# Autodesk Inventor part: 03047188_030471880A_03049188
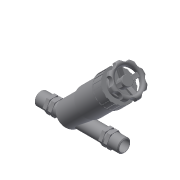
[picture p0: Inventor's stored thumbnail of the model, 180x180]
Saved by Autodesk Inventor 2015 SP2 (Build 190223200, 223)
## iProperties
Created: 2017-05
Part Number: 03047188_030471880A_03049188
Material: Generic
Description: PLASSON ANGLE SEAT VALVE 1.1/4"-1.1/4"
Document SubType Name: Modeling
Designer: KIM
Density: 1 g/cm^3
Appearance: Default
Author: KIM
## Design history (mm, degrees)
derived "03049.ipt"
feature "Solid1::03049.ipt"
tag "TaggingFeature1"
body "Solid1"
other parameters: "d0" = 225, "d1" = 47.803, "d3" = 38.2424, "d4" = 22, "d5" = 22, "d6" = 22.5, "d8" = 2.25, "d12" = 0, "d14" = -11.25, "d15" = 4.5, "d16" = 0, "d17" = 61.479, "d18" = 7.452, "d19" = 204.93, "d20" = 69.8625, "d21" = 135 deg, "d22" = 79.1775, "d23" = 37.26, "d24" = 88.4925, "d25" = 22.356, "d26" = 90 deg, "d27" = 65.205, "d28" = 70 deg, "d29" = 27.945, "d30" = 22.356, "d31" = 27.945, "d32" = 93.15, "d33" = 65.205, "d34" = 135 deg, "d35" = 2, "d36" = 186.3, "d39" = 78.75, "d40" = 2.07, "d41" = 1, "d42" = 1, "d43" = 6.21, "d44" = 6.21, "d46" = 0, "d48" = 360 deg, "d50" = 1.035, "d51" = 1.035, "d53" = 360 deg, "d69" = 79.1775, "d70" = 6.21, "d71" = 6.21, "d72" = 12.42, "d74" = 0, "d75" = 1.035, "d77" = 360 deg, "d80" = 85.83773, "d81" = 8.28, "d82" = 4.14, "d83" = 33.534, "d84" = 0, "d86" = 360 deg, "d88" = 2.07, "d91" = 207, "H_" = 225, "R_" = 47.803, "l_2" = 22, "A_" = 207, "d13" = 22.5, "d67" = 93.15, "d68" = 65.205, "d79" = 88.4925
